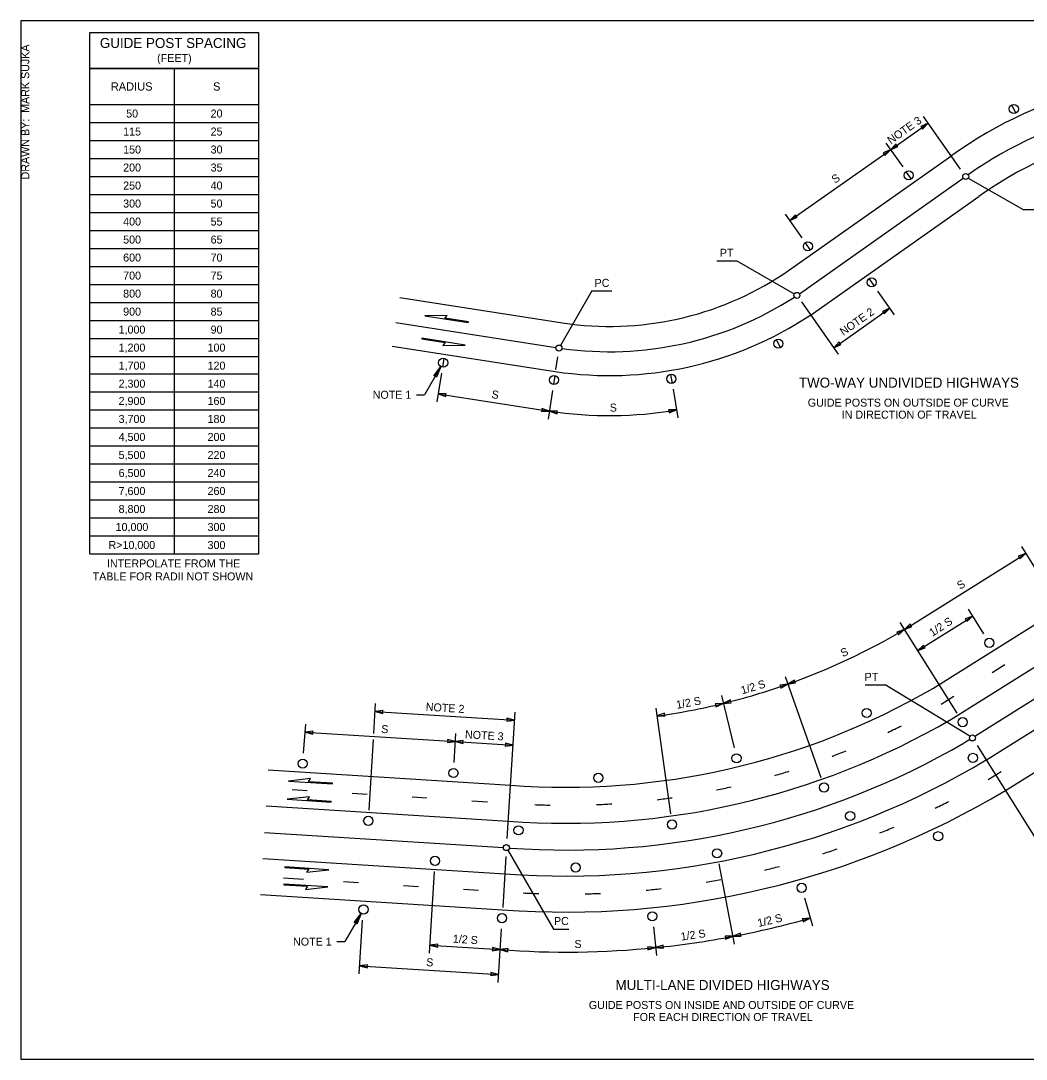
# Model space of a CAD drawing. Extents: x 99862 to 103151, y 100000 to 102076.
# Drawn here: x 99862 to 101871, y 100000 to 102076 of the extents above; entities that cross this region are included whole.
import ezdxf

# ---------------------------------------------------------------- set-up
doc = ezdxf.new("R2010")
doc.units = 0
for name, color, linetype in [('Default', 7, 'Continuous'), ('Level 1', 7, 'Continuous'), ('Level 14', 7, 'Continuous'), ('Level 15', 7, 'Continuous'), ('Level 19', 7, 'Continuous'), ('Level 2', 7, 'Continuous'), ('Level 20', 7, 'Continuous'), ('Level 39', 7, 'Continuous'), ('Level 4', 7, 'Continuous'), ('Level 60', 7, 'Continuous'), ('Level 62', 7, 'Continuous'), ('Level 7', 7, 'Continuous')]:
    doc.layers.add(name, color=color, linetype=linetype)

msp = doc.modelspace()

# ---------------------------------------------------------------- linework, layer by layer
at = {"layer": 'Default'}
for p, q in [((101385.1, 101568.5), (101722.7, 101806.3)), ((101418.1, 101529.7), (101745.6, 101760.6)), ((101439.3, 101486.5), (101776.8, 101724.3)), ((100619.3, 101522.3), (100944.9, 101471.4)), ((100611.5, 101472.3), (100931.4, 101422.3)), ((100604.2, 101425.2), (100930.2, 101374.2))]:
    msp.add_line(p, q, dxfattribs=at)
for points in [[(100570.2, 100694.7), (100585.7, 100690.7), (100585.2, 100693.8), (100586.1, 100696.9)], [(100849, 100677.2), (100833.5, 100681.2), (100834.1, 100678.1), (100833.2, 100675.1)]]:
    msp.add_lwpolyline(points, close=True, dxfattribs=at)
msp.add_circle((100832.5, 100422.6), 6.06, dxfattribs=at)
for centre, radius, start, end in [((102223.1, 101108), 859.1, 81.6721, 125.6265), ((102222.9, 101104.9), 811, 82.1094, 125.1975), ((102221.3, 101104), 763, 81.6721, 125.6265), ((101038.3, 102094.3), 629.9, 261.4676, 303.4132), ((101038.3, 102094.3), 680.4, 261.9827, 302.9096), ((101038.3, 102094.3), 728.1, 261.4676, 303.4132)]:
    msp.add_arc(centre, radius, start, end, dxfattribs=at)
at = {"layer": 'Level 1'}
for p, q in [((101850.6, 101890.9), (101842.6, 101907.4)), ((101641.8, 101759.1), (101631.3, 101773.7)), ((101440.4, 101617.2), (101430, 101631.9)), ((101557.2, 101559.9), (101567.7, 101545)), ((101371.7, 101438.1), (101380.1, 101421.9)), ((100707.4, 101401.1), (100704.6, 101383)), ((100929, 101366.4), (100926.4, 101348.4)), ((101160.7, 101368.4), (101163.7, 101350.6)), ((101549.2, 100747.9), (101589.2, 100747.9)), ((100835.5, 100417.4), (100926.5, 100259.8)), ((100926.5, 100259.8), (100957.6, 100259.8))]:
    msp.add_line(p, q, dxfattribs=at)
msp.add_lwpolyline([(99862, 99999.5), (103151, 99999.5), (103151, 102075.5), (99862, 102075.5)], close=True, dxfattribs=at)
for centre, radius in [((101846.6, 101899.2), 9.14), ((101636.6, 101766.4), 8.97), ((101750.5, 101764.2), 6.06), ((101435, 101624.5), 9.04), ((101562.4, 101552.5), 9.2), ((101413, 101526.4), 6.06), ((101375.9, 101430), 9.14), ((100937.4, 101421.2), 6.06), ((100706.1, 101392), 9.14), ((100927.6, 101357.4), 9.14), ((101162, 101359.6), 9.14), ((101797.8, 100831.9), 9.14), ((101552.4, 100691.5), 9.14), ((101744.4, 100673.4), 9.14), ((101764, 100641.9), 6.06), ((101292.3, 100601.1), 9.14), ((101764.8, 100601.9), 9.14), ((100425.5, 100590.5), 9.14), ((100726.7, 100571.7), 9.14), ((101016.1, 100562), 9.14), ((101467.4, 100542.7), 9.14), ((100556.4, 100476.1), 9.14), ((101519.6, 100485.6), 9.14), ((100856.8, 100457.2), 9.14), ((101163.5, 100468.8), 9.14), ((101695.5, 100445.3), 9.14), ((101253.6, 100411.1), 9.14), ((100689.8, 100396.1), 9.14), ((100970.8, 100382.8), 9.14), ((101422.5, 100342.2), 9.14), ((100546.9, 100298.8), 9.14), ((101124, 100285.3), 9.14), ((100823.8, 100281.5), 9.14)]:
    msp.add_circle(centre, radius, dxfattribs=at)
at = {"layer": 'Level 14'}
for p, q in [((101600.1, 101817.8), (101675.2, 101870.7)), ((101740.1, 101779), (101666, 101883.8)), ((101590.8, 101830.8), (101624.5, 101783.5)), ((101398.9, 101676), (101600.1, 101817.8)), ((101755.7, 101761.1), (101865.2, 101697.9)), ((101389.7, 101689.1), (101423.1, 101641.8)), ((101865.2, 101697.9), (101905.2, 101697.9)), ((101252.9, 101595.6), (101292.9, 101595.6)), ((101292.9, 101595.6), (101407.8, 101529.3)), ((101003.3, 101535.5), (100940.4, 101426.5)), ((101003.3, 101535.5), (101043.3, 101535.5)), ((101607.9, 101487.8), (101574.7, 101535.2)), ((101422.2, 101513.4), (101495.8, 101408.9)), ((101486.6, 101421.9), (101598.7, 101500.9)), ((100934.4, 101403.5), (100930.7, 101378.3)), ((100702.7, 101371.1), (100693.7, 101314)), ((100696.2, 101329.8), (100918.5, 101295.1)), ((100924.7, 101336.5), (100916.3, 101279.2)), ((101165.7, 101338.8), (101175.3, 101281.6)), ((101861.9, 101024.2), (101974.7, 100842.5)), ((101627.9, 100858.8), (101870.3, 101010.6)), ((101786.6, 100849.8), (101756.1, 100899)), ((101654.5, 100816.4), (101764.5, 100885.3)), ((101733.1, 100691.2), (101619.4, 100872.3)), ((101389.4, 100764.4), (101460.6, 100562.7)), ((100567.5, 100650.8), (100571.1, 100710.7)), ((101262.2, 100726.5), (101287.6, 100621.7)), ((100570.2, 100694.7), (100849, 100677.2)), ((100833.9, 100440.6), (100850.1, 100693.2)), ((101131.4, 100701.6), (101160.6, 100489.8)), ((100427.1, 100611.6), (100431.5, 100669.4)), ((100430.2, 100653.4), (100730.4, 100634.6)), ((100728, 100592.8), (100731.3, 100650.5)), ((100558.3, 100497.2), (100566.8, 100638.8)), ((100730.5, 100634.6), (100845.9, 100627.3)), ((101907.7, 100413.3), (101773.7, 100626.7)), ((100831.7, 100404.6), (100825.3, 100302.5)), ((100678.9, 100211.4), (100688.6, 100375)), ((101288.5, 100229.5), (101257.5, 100390.3)), ((101428.3, 100321.9), (101444.1, 100266.3)), ((100538.2, 100170.1), (100545.1, 100277.8)), ((100815.9, 100152.7), (100822.7, 100260.3)), ((101126.4, 100264.3), (101132.3, 100206.8)), ((100679.8, 100227.4), (100820, 100218.6)), ((100539.2, 100186.1), (100816.9, 100168.7))]:
    msp.add_line(p, q, dxfattribs=at)
for points in [[(101675.2, 101870.7), (101660.6, 101864.2), (101663, 101862.1), (101664.1, 101859.1)], [(101600.1, 101817.8), (101614.7, 101824.3), (101612.3, 101826.4), (101611.2, 101829.3)], [(101600.1, 101817.8), (101585.4, 101811.2), (101587.8, 101809.1), (101589, 101806.2)], [(101398.9, 101676), (101413.5, 101682.6), (101411.1, 101684.7), (101410, 101687.6)], [(101598.7, 101500.9), (101584.1, 101494.4), (101586.5, 101492.3), (101587.6, 101489.4)], [(101486.6, 101421.9), (101501.2, 101428.5), (101498.8, 101430.6), (101497.7, 101433.5)], [(100696.2, 101329.8), (100711.2, 101324.4), (100711, 101327.5), (100712.2, 101330.4)], [(100918.5, 101295.1), (100903.5, 101300.5), (100903.7, 101297.4), (100902.5, 101294.4)], [(100918.5, 101295.1), (100933.7, 101289.9), (100933.4, 101293), (100934.5, 101296)], [(101172.7, 101297.4), (101156.6, 101297.8), (101157.9, 101294.9), (101157.7, 101291.8)], [(101764.5, 100885.3), (101749.5, 100879.6), (101751.8, 100877.4), (101752.8, 100874.4)], [(101627.9, 100858.8), (101612.8, 100853.4), (101615, 100851.1), (101616, 100848.1)], [(101654.5, 100816.4), (101669.5, 100822.2), (101667.2, 100824.4), (101666.2, 100827.4)], [(101394.8, 100749.3), (101378.9, 100747.1), (101380.6, 100744.4), (101380.9, 100741.2)], [(101394.8, 100749.3), (101410.6, 100751.8), (101408.9, 100754.5), (101408.5, 100757.6)], [(101265.6, 100710.9), (101249.6, 100710.2), (101251, 100707.4), (101251.1, 100704.2)], [(101266, 100710.9), (101282, 100711.8), (101280.6, 100714.6), (101280.5, 100717.8)], [(101133.5, 100685.8), (101149.6, 100685), (101148.4, 100687.9), (101148.7, 100691.1)], [(100679.8, 100227.4), (100695.3, 100223.3), (100694.7, 100226.4), (100695.7, 100229.4)], [(100816.9, 100168.7), (100801.4, 100172.8), (100801.9, 100169.7), (100801, 100166.7)]]:
    msp.add_lwpolyline(points, close=True, dxfattribs=at)
for centre, radius, start, end in [((101038.3, 102094.3), 808.1, 261.4813, 279.57), ((100950, 102000.1), 1327.5, 289.5746, 300.72), ((100948.7, 102009.5), 1336.7, 283.7313, 289.4928), ((100951.7, 102000.9), 1327.7, 277.8713, 283.6759), ((100951.7, 102000.9), 1787.2, 280.763, 285.8466), ((100951.7, 102000.9), 1787.2, 275.7455, 280.763), ((100951.7, 102000.9), 1787.2, 265.7745, 275.7455)]:
    msp.add_arc(centre, radius, start, end, dxfattribs=at)
at = {"layer": 'Level 15'}
for p, q in [((100701.5, 101384.1), (100669, 101327.8)), ((100653, 101327.8), (100669, 101327.8)), ((100542.3, 100290.9), (100509.8, 100234.6)), ((100493.8, 100234.6), (100509.8, 100234.6))]:
    msp.add_line(p, q, dxfattribs=at)
for points in [[(100701.5, 101384.1), (100692.7, 101362.8), (100690.6, 101365.2), (100687.5, 101365.8)], [(100542.3, 100290.9), (100533.5, 100269.7), (100531.4, 100272.1), (100528.3, 100272.7)]]:
    msp.add_lwpolyline(points, close=True, dxfattribs=at)
at = {"layer": 'Level 2'}
for points in [[(100756.5, 101473.4), (100709.4, 101480.8), (100714.1, 101486.6), (100669.4, 101485.8), (100756.3, 101472.2)], [(100663.2, 101439.6), (100710.3, 101432.3), (100705.6, 101426.4), (100750.2, 101427.3), (100663.3, 101440.9)], [(100484.8, 100551.1), (100437.1, 100554.1), (100441.3, 100560.4), (100396.9, 100555.4), (100484.7, 100549.9)], [(100482.5, 100514.8), (100434.9, 100517.8), (100439, 100524.1), (100394.6, 100519.1), (100482.4, 100513.6)], [(100389.8, 100382.7), (100437.4, 100379.7), (100433.2, 100373.4), (100477.6, 100378.4), (100389.8, 100383.9)], [(100387.6, 100348.4), (100435.2, 100345.4), (100431.1, 100339.1), (100475.4, 100344.1), (100387.7, 100349.6)]]:
    msp.add_lwpolyline(points, close=True, dxfattribs=at)
at = {"layer": 'Level 20'}
msp.add_line((101758.8, 100645.1), (101589.2, 100747.9), dxfattribs=at)
at = {"layer": 'Level 39'}
for p, q in [((100168.6, 101980.1), (100168.6, 101009.5)), ((99999.9, 101908.1), (100337.4, 101908.1)), ((99999.9, 101872.1), (100337.4, 101872.1)), ((99999.9, 101836.1), (100337.4, 101836.1)), ((99999.9, 101800.1), (100337.4, 101800.1)), ((99999.9, 101764.1), (100337.4, 101764.1)), ((99999.9, 101728.1), (100337.4, 101728.1)), ((99999.9, 101692.1), (100337.4, 101692.1)), ((99999.9, 101656.1), (100337.4, 101656.1)), ((99999.9, 101620.1), (100337.4, 101620.1)), ((99999.9, 101584.1), (100337.4, 101584.1)), ((99999.9, 101548.1), (100337.4, 101548.1)), ((99999.9, 101512.1), (100337.4, 101512.1)), ((99999.9, 101476.1), (100337.4, 101476.1)), ((99999.9, 101440.1), (100337.4, 101440.1)), ((99999.9, 101404.1), (100337.4, 101404.1)), ((100001.1, 101369.5), (100337.4, 101369.5)), ((100001.1, 101333.5), (100338.6, 101333.5)), ((100001.1, 101297.5), (100338.6, 101297.5)), ((100001.1, 101261.5), (100338.6, 101261.5)), ((100001.1, 101225.5), (100338.6, 101225.5)), ((100001.1, 101189.5), (100338.6, 101189.5)), ((100001.1, 101153.5), (100338.6, 101153.5)), ((100001.1, 101117.5), (100338.6, 101117.5)), ((100001.1, 101081.5), (100338.6, 101081.5)), ((100001.1, 101045.5), (100338.6, 101045.5))]:
    msp.add_line(p, q, dxfattribs=at)
msp.add_lwpolyline([(99999.9, 102052.1), (100337.4, 102052.1), (100337.4, 101980.1), (99999.9, 101980.1)], close=True, dxfattribs=at)
for points in [[(99999.9, 101009.5), (99999.9, 101980.1), (100337.4, 101980.1), (100337.4, 101009.5)], [(100337.4, 101009.5), (100001.1, 101009.5)]]:
    msp.add_lwpolyline(points, dxfattribs=at)
at = {"layer": 'Level 4'}
for p, q in [((101684.6, 100740.9), (102048.6, 100968.9)), ((101720.8, 100678.6), (102086.8, 100907.9)), ((101768.9, 100645.6), (102115.3, 100862.4)), ((101791.7, 100597.9), (102142.8, 100818.5)), ((101803.1, 100772.7), (101828.5, 100788.6)), ((101830, 100536.9), (102181, 100757.5)), ((101701.4, 100709), (101726.8, 100725)), ((101747.8, 100632.4), (101758.6, 100639.2)), ((100356.7, 100577.8), (100840.8, 100547.5)), ((101795.6, 100558.6), (101821, 100574.5)), ((100404.4, 100538.8), (100434.3, 100536.9)), ((100524.1, 100531.3), (100554.1, 100529.4)), ((100643.9, 100523.8), (100673.8, 100521.9)), ((100352.2, 100506), (100836.2, 100475.6)), ((100763.7, 100516.3), (100795, 100514.3)), ((100348.9, 100452.6), (100826.4, 100422.5)), ((100345.6, 100400.7), (100829.5, 100370.3)), ((100387.3, 100362), (100426.7, 100359.5)), ((100507, 100354.5), (100537, 100352.6)), ((100626.8, 100346.9), (100656.7, 100345.1)), ((100746.6, 100339.4), (100776.5, 100337.5)), ((100341.1, 100328.8), (100825, 100298.4))]:
    msp.add_line(p, q, dxfattribs=at)
for points in [[(101870.3, 101010.6), (101855.3, 101004.9), (101857.6, 101002.7), (101858.6, 100999.7)], [(101627.9, 100858.8), (101642.9, 100864.5), (101640.6, 100866.7), (101639.6, 100869.7)], [(100430.2, 100653.4), (100445.7, 100649.4), (100445.2, 100652.5), (100446.1, 100655.5)], [(100730.5, 100634.6), (100715, 100638.6), (100715.5, 100635.5), (100714.6, 100632.5)], [(100730.5, 100634.6), (100746, 100630.5), (100745.4, 100633.6), (100746.4, 100636.7)], [(100845.9, 100627.3), (100830.4, 100631.4), (100830.9, 100628.3), (100830, 100625.2)], [(101439.7, 100281.7), (101423.8, 100280.4), (101425.3, 100277.7), (101425.4, 100274.5)], [(101285.5, 100245.2), (101301.5, 100245.2), (101300.2, 100248.1), (101300.3, 100251.3)], [(101285.5, 100245.2), (101269.5, 100245.4), (101270.7, 100242.5), (101270.6, 100239.3)], [(100820, 100218.6), (100804.5, 100222.7), (100805.1, 100219.5), (100804.1, 100216.5)], [(100820, 100218.6), (100835.5, 100214.5), (100835, 100217.6), (100835.9, 100220.6)], [(101130.6, 100222.7), (101114.7, 100224.3), (101115.7, 100221.3), (101115.3, 100218.2)], [(101130.6, 100222.7), (101146.6, 100221.4), (101145.5, 100224.3), (101145.9, 100227.5)], [(100539.2, 100186.1), (100554.7, 100182), (100554.2, 100185.2), (100555.1, 100188.2)]]:
    msp.add_lwpolyline(points, close=True, dxfattribs=at)
for radius, start, end in [(1457.7, 265.6345, 300.1812), (1529.7, 265.6681, 300.1812), (1493.7, 295.5082, 296.6653), (1583.3, 265.8973, 300.1812), (1493.7, 290.8482, 292.019), (1635.2, 265.7143, 300.9092), (1493.7, 286.2208, 287.3732), (1493.7, 281.6165, 282.7677), (1707.2, 265.744, 300.9607), (1493.7, 276.9985, 278.156), (1493.7, 267.5959, 268.7903), (1493.7, 272.3362, 273.5077), (1671.2, 296.2055, 297.2384), (1671.2, 292.0509, 293.0937), (1671.2, 287.878, 288.91), (1671.2, 283.7604, 284.7889), (1671.2, 279.6429, 280.6734), (1671.2, 275.5042, 276.5421), (1671.2, 267.071, 268.1416), (1671.2, 271.3218, 272.3728)]:
    msp.add_arc((100951.7, 102000.9), radius, start, end, dxfattribs=at)
at = {"layer": 'Level 60'}
msp.add_line((99862, 99999.5), (99862, 99999.5), dxfattribs=at)

# ---------------------------------------------------------------- texts
at = {"layer": 'Level 1'}
for s, p in [('PT', (101259.2, 101603.6)), ('PC', (101008.8, 101543.5)), ('NOTE 1', (100565.3, 101319.8)), ('PT', (101548.4, 100755.9)), ('PC', (100927.6, 100267.8)), ('NOTE 1', (100406.1, 100226.6))]:
    msp.add_text(s, height=16, dxfattribs=at).set_placement(p)
for s, rotation, p in [('S', 32.032, (101739.2, 100937.9)), ('S', 25.1739, (101504.7, 100803)), ('NOTE 2', 356.5103, (100671, 100696.3)), ('S', 356.5913, (100582, 100651.9)), ('NOTE 3', 356.5743, (100749.3, 100641.3)), ('S', 0.7536, (100968.6, 100221.8)), ('S', 356.442, (100671.9, 100185.8))]:
    msp.add_text(s, height=16, rotation=rotation, dxfattribs=at).set_placement(p)
at = {"layer": 'Level 19'}
for s, height, p in [('(FEET)', 16, (100134.5, 101993.1)), ('50', 16, (100072.6, 101882.1)), ('20', 16, (100241.4, 101882.1)), ('115', 16, (100066.6, 101846.1)), ('25', 16, (100241.4, 101846.1)), ('150', 16, (100066.6, 101810.1)), ('30', 16, (100241.4, 101810.1)), ('200', 16, (100066.6, 101774.1)), ('35', 16, (100241.4, 101774.1)), ('250', 16, (100066.6, 101738.1)), ('40', 16, (100241.4, 101738.1)), ('300', 16, (100066.6, 101702.1)), ('50', 16, (100241.4, 101702.1)), ('400', 16, (100066.6, 101666.1)), ('55', 16, (100241.4, 101666.1)), ('500', 16, (100066.6, 101630.1)), ('65', 16, (100241.4, 101630.1)), ('600', 16, (100066.6, 101594.1)), ('70', 16, (100241.4, 101594.1)), ('700', 16, (100066.6, 101558.1)), ('75', 16, (100241.4, 101558.1)), ('800', 16, (100066.6, 101522.1)), ('80', 16, (100241.4, 101522.1)), ('900', 16, (100066.6, 101486.1)), ('85', 16, (100241.4, 101486.1)), ('1,000', 16, (100057.5, 101450.1)), ('90', 16, (100241.4, 101450.1)), ('1,200', 16, (100057.5, 101414.1)), ('100', 16, (100235.3, 101414.1)), ('1,700', 16, (100057.5, 101378.1)), ('120', 16, (100235.3, 101378.1)), ('2,300', 16, (100057.5, 101342.1)), ('140', 16, (100235.3, 101342.1)), ('TWO-WAY UNDIVIDED HIGHWAYS', 20, (101417.1, 101342.1)), ('2,900', 16, (100057.5, 101307.5)), ('160', 16, (100235.3, 101307.5)), ('GUIDE POSTS ON OUTSIDE OF CURVE', 16, (101434.8, 101304.1)), ('IN DIRECTION OF TRAVEL', 16, (101502.7, 101280.1)), ('3,700', 16, (100057.5, 101271.5)), ('180', 16, (100235.3, 101271.5)), ('4,500', 16, (100057.5, 101235.5)), ('200', 16, (100235.3, 101235.5)), ('5,500', 16, (100057.5, 101199.5)), ('220', 16, (100235.3, 101199.5)), ('6,500', 16, (100057.5, 101163.5)), ('240', 16, (100235.3, 101163.5)), ('7,600', 16, (100057.5, 101127.5)), ('260', 16, (100235.3, 101127.5)), ('8,800', 16, (100057.5, 101091.5)), ('280', 16, (100235.3, 101091.5)), ('10,000', 16, (100051.5, 101055.5)), ('300', 16, (100235.3, 101055.5)), ('R>10,000', 16, (100037.3, 101019.5)), ('300', 16, (100235.3, 101019.5)), ('INTERPOLATE FROM THE', 16, (100034.3, 100982.7)), ('TABLE FOR RADII NOT SHOWN', 16, (100005.6, 100956.7)), ('MULTI-LANE DIVIDED HIGHWAYS', 20, (101050.6, 100137.9)), ('GUIDE POSTS ON INSIDE AND OUTSIDE OF CURVE', 16, (100997.3, 100099.9)), ('FOR EACH DIRECTION OF TRAVEL', 16, (101085.8, 100075.9))]:
    msp.add_text(s, height=height, dxfattribs=at).set_placement(p)
at = {"layer": 'Level 20'}
for s, height, p in [('GUIDE POST SPACING', 20, (100020.1, 102021.1)), ('RADIUS', 16.5, (100041.9, 101935.9)), ('S', 16.5, (100246.2, 101935.9))]:
    msp.add_text(s, height=height, dxfattribs=at).set_placement(p)
for s, rotation, p in [('NOTE 3', 35.1652, (101600.8, 101828.1)), ('S', 35.1652, (101489.4, 101749.6)), ('NOTE 2', 35.1653, (101506, 101445.4)), ('S', 351.1126, (100802, 101321.4)), ('S', 0.5256, (101039, 101294.1))]:
    msp.add_text(s, height=16, rotation=rotation, dxfattribs=at).set_placement(p)
at = {"layer": 'Level 62'}
msp.add_text('DRAWN BY:  MARK SUJKA', height=16, rotation=90, dxfattribs=at).set_placement((99879, 101758.3))
msp.add_text('DRAWN BY:  MARK SUJKA', height=16, rotation=90, dxfattribs=at).set_placement((99879, 101758.3))
at = {"layer": 'Level 7'}
for rotation, p in [(32.8098, (101683.8, 100843.9)), (16.5782, (101303.8, 100728.8)), (10.7735, (101173.5, 100699.8)), (13.3045, (101336.5, 100263.7)), (8.253, (101182, 100236.5)), (356.1903, (100725.1, 100232.7))]:
    msp.add_text('1/2 S', height=16, rotation=rotation, dxfattribs=at).set_placement(p)

doc.saveas('drawing.dxf')
